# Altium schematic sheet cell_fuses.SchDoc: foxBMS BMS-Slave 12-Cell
size A3; DocumentNumber: 3; SheetNumber: 3; SheetTotal: 15; AUTHOR: Fraunhofer IISB foxBMS Team; SheetDescription: Cell Voltage Sense Fuses
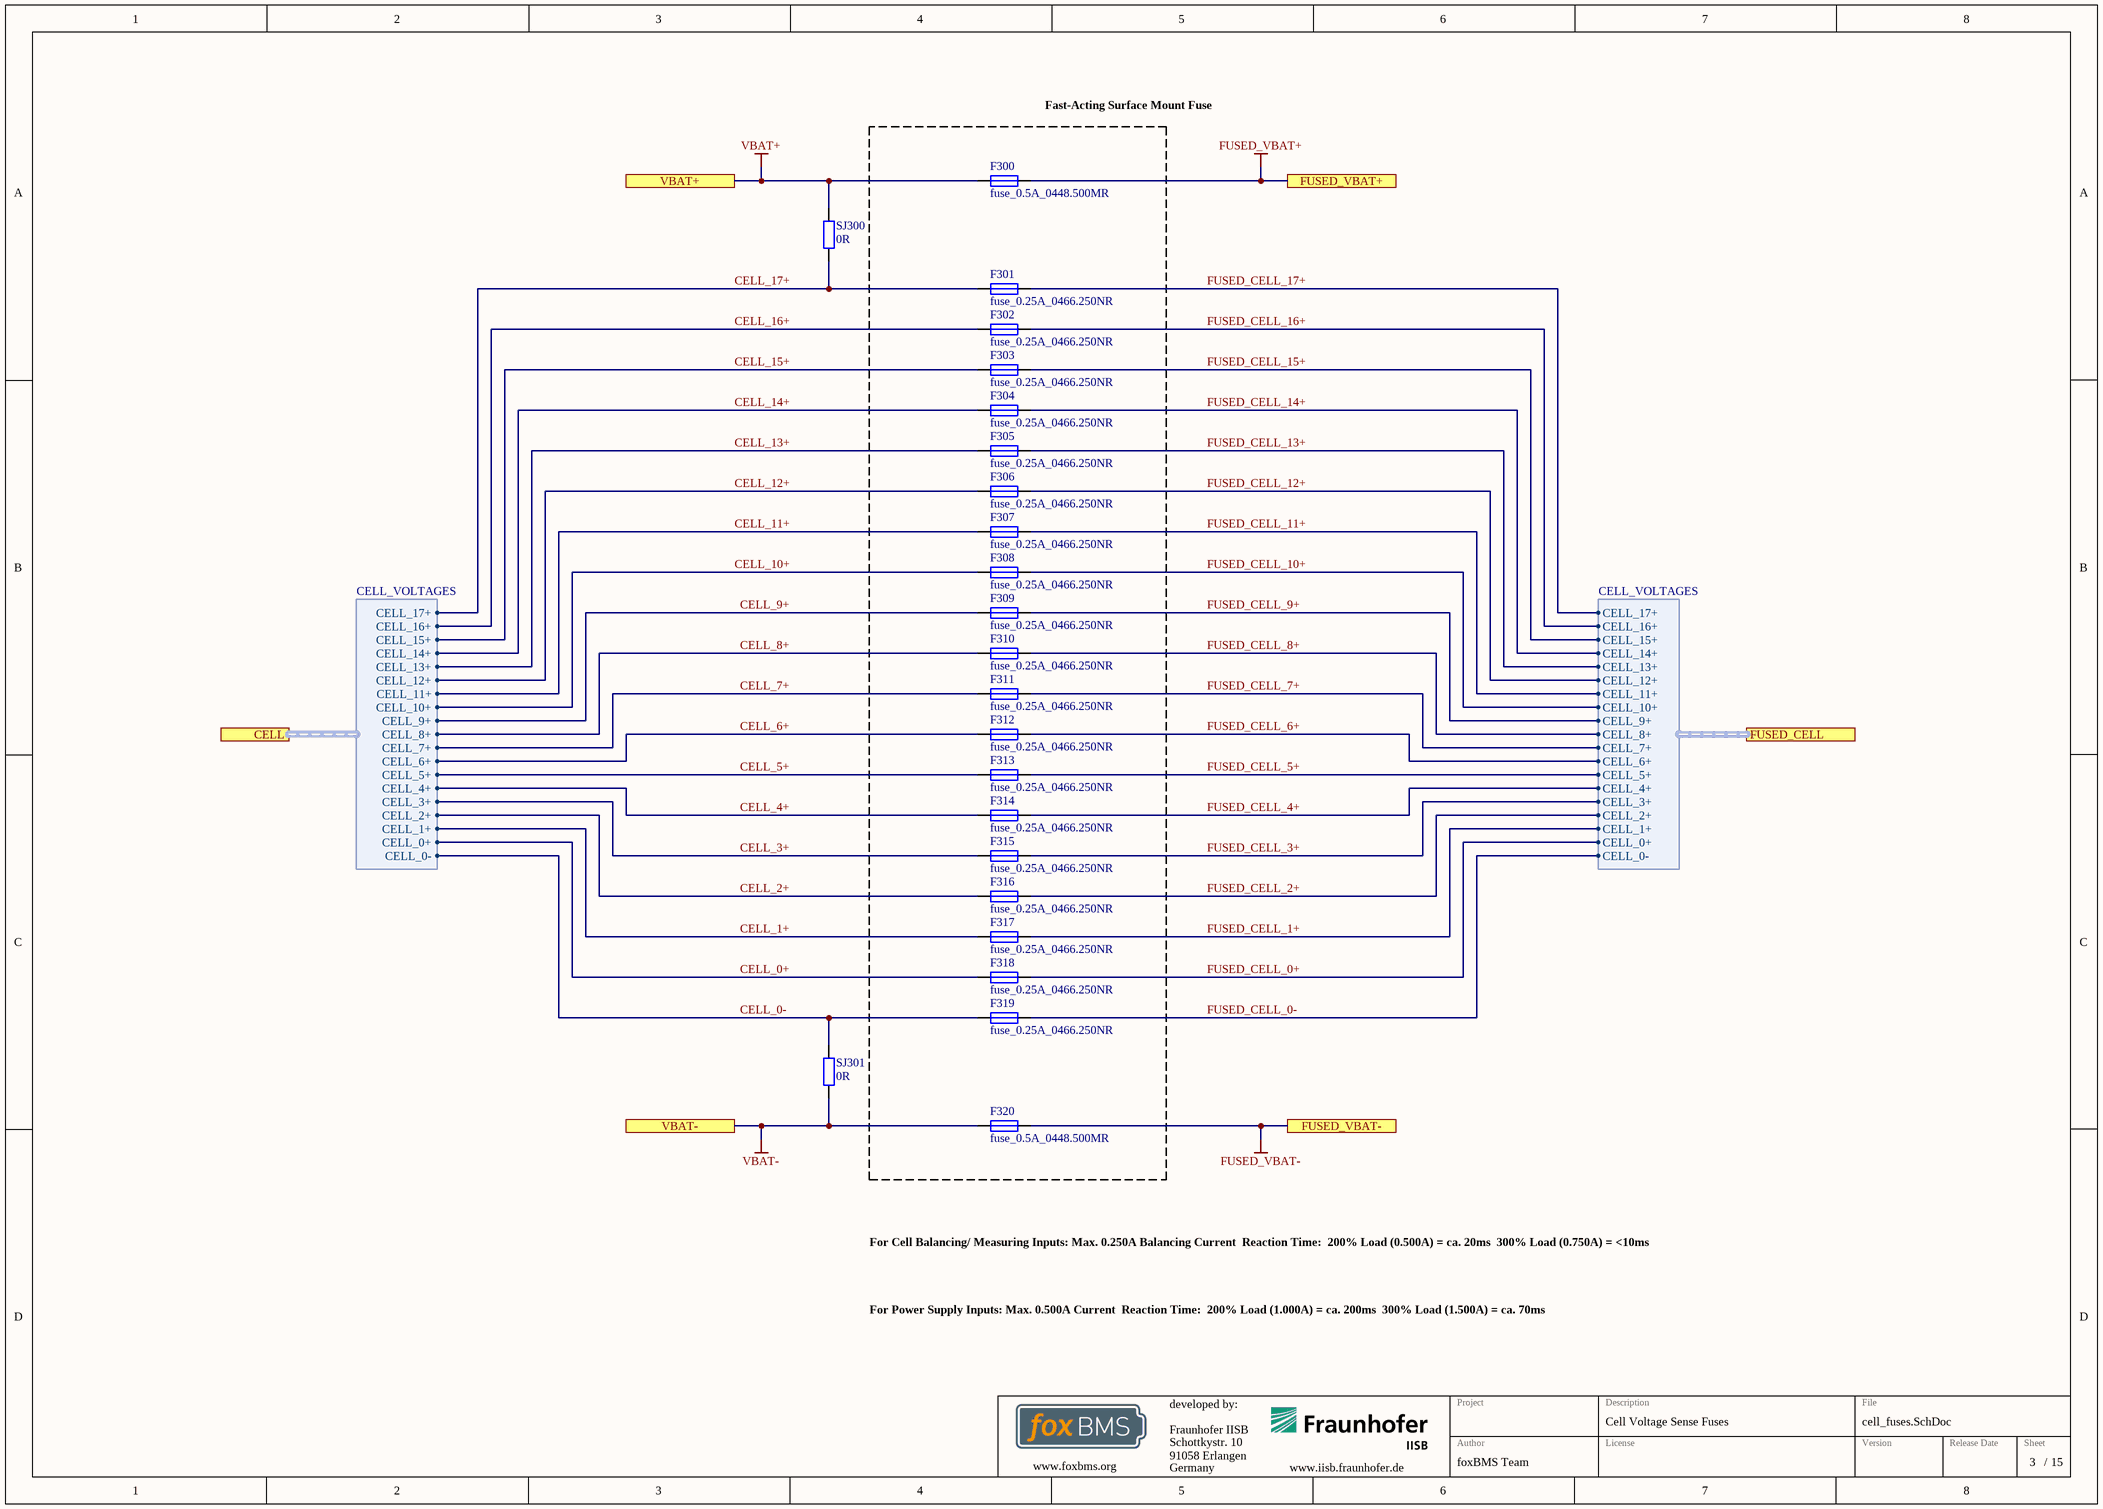
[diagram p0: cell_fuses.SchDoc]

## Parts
F300  fuse_0.5A_0448.500MR  [LITTLEFUSE_448]
F301  fuse_0.25A_0466.250NR  [LITTLEFUSE_466]
F302  fuse_0.25A_0466.250NR  [LITTLEFUSE_466]
F303  fuse_0.25A_0466.250NR  [LITTLEFUSE_466]
F304  fuse_0.25A_0466.250NR  [LITTLEFUSE_466]
F305  fuse_0.25A_0466.250NR  [LITTLEFUSE_466]
F306  fuse_0.25A_0466.250NR  [LITTLEFUSE_466]
F307  fuse_0.25A_0466.250NR  [LITTLEFUSE_466]
F308  fuse_0.25A_0466.250NR  [LITTLEFUSE_466]
F309  fuse_0.25A_0466.250NR  [LITTLEFUSE_466]
F310  fuse_0.25A_0466.250NR  [LITTLEFUSE_466]
F311  fuse_0.25A_0466.250NR  [LITTLEFUSE_466]
F312  fuse_0.25A_0466.250NR  [LITTLEFUSE_466]
F313  fuse_0.25A_0466.250NR  [LITTLEFUSE_466]
F314  fuse_0.25A_0466.250NR  [LITTLEFUSE_466]
F315  fuse_0.25A_0466.250NR  [LITTLEFUSE_466]
F316  fuse_0.25A_0466.250NR  [LITTLEFUSE_466]
F317  fuse_0.25A_0466.250NR  [LITTLEFUSE_466]
F318  fuse_0.25A_0466.250NR  [LITTLEFUSE_466]
F319  fuse_0.25A_0466.250NR  [LITTLEFUSE_466]
F320  fuse_0.5A_0448.500MR  [LITTLEFUSE_448]
SJ300  0R  [RESC1608X05N]
SJ301  0R  [RESC1608X05N]

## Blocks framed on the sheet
Fast-Acting Surface Mount Fuse: F300-F320

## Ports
CELL (harness CELL_VOLTAGES), FUSED_CELL (harness CELL_VOLTAGES), FUSED_VBAT+, FUSED_VBAT-, VBAT+, VBAT-

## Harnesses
CELL_VOLTAGES: CELL_0-, CELL_0+, CELL_1+, CELL_10+, CELL_11+, CELL_12+, CELL_13+, CELL_14+, CELL_15+, CELL_16+, CELL_17+, CELL_2+, CELL_3+, CELL_4+, CELL_5+, CELL_6+, CELL_7+, CELL_8+, CELL_9+

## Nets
FUSED_VBAT+: F300.2 ; port FUSED_VBAT+
FUSED_VBAT-: F320.2 ; port FUSED_VBAT-
VBAT+: F300.1 SJ300.1 ; port VBAT+
VBAT-: F320.1 SJ301.2 ; port VBAT-
CELL_0+: F318.1 ; port CELL.CELL_0+
CELL_0-: F319.1 SJ301.1 ; port CELL.CELL_0-
CELL_1+: F317.1 ; port CELL.CELL_1+
CELL_2+: F316.1 ; port CELL.CELL_2+
CELL_3+: F315.1 ; port CELL.CELL_3+
CELL_4+: F314.1 ; port CELL.CELL_4+
CELL_5+: F313.1 ; port CELL.CELL_5+
CELL_6+: F312.1 ; port CELL.CELL_6+
CELL_7+: F311.1 ; port CELL.CELL_7+
CELL_8+: F310.1 ; port CELL.CELL_8+
CELL_9+: F309.1 ; port CELL.CELL_9+
CELL_10+: F308.1 ; port CELL.CELL_10+
CELL_11+: F307.1 ; port CELL.CELL_11+
CELL_12+: F306.1 ; port CELL.CELL_12+
CELL_13+: F305.1 ; port CELL.CELL_13+
CELL_14+: F304.1 ; port CELL.CELL_14+
CELL_15+: F303.1 ; port CELL.CELL_15+
CELL_16+: F302.1 ; port CELL.CELL_16+
CELL_17+: F301.1 SJ300.2 ; port CELL.CELL_17+
FUSED_CELL_0+: F318.2 ; port FUSED_CELL.CELL_0+
FUSED_CELL_0-: F319.2 ; port FUSED_CELL.CELL_0-
FUSED_CELL_1+: F317.2 ; port FUSED_CELL.CELL_1+
FUSED_CELL_2+: F316.2 ; port FUSED_CELL.CELL_2+
FUSED_CELL_3+: F315.2 ; port FUSED_CELL.CELL_3+
FUSED_CELL_4+: F314.2 ; port FUSED_CELL.CELL_4+
FUSED_CELL_5+: F313.2 ; port FUSED_CELL.CELL_5+
FUSED_CELL_6+: F312.2 ; port FUSED_CELL.CELL_6+
FUSED_CELL_7+: F311.2 ; port FUSED_CELL.CELL_7+
FUSED_CELL_8+: F310.2 ; port FUSED_CELL.CELL_8+
FUSED_CELL_9+: F309.2 ; port FUSED_CELL.CELL_9+
FUSED_CELL_10+: F308.2 ; port FUSED_CELL.CELL_10+
FUSED_CELL_11+: F307.2 ; port FUSED_CELL.CELL_11+
FUSED_CELL_12+: F306.2 ; port FUSED_CELL.CELL_12+
FUSED_CELL_13+: F305.2 ; port FUSED_CELL.CELL_13+
FUSED_CELL_14+: F304.2 ; port FUSED_CELL.CELL_14+
FUSED_CELL_15+: F303.2 ; port FUSED_CELL.CELL_15+
FUSED_CELL_16+: F302.2 ; port FUSED_CELL.CELL_16+
FUSED_CELL_17+: F301.2 ; port FUSED_CELL.CELL_17+

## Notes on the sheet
- For Cell Balancing/ Measuring Inputs: Max. 0.250A Balancing Current
  Reaction Time:
  200% Load (0.500A) = ca. 20ms
  300% Load (0.750A) = <10ms
- For Power Supply Inputs: Max. 0.500A Current
  Reaction Time:
  200% Load (1.000A) = ca. 200ms
  300% Load (1.500A) = ca. 70ms

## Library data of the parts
F300 F320 = fuse_0.5A_0448.500MR: Fuse, Surface Mount, NANO2 Series, 500 mA, 125 VAC, 32 VDC, Very Fast Acting, SMD; Manufacturer: Littlefuse; Automotive Qualified: False
F301-F319 = fuse_0.25A_0466.250NR: Fuse, Surface Mount, 466 Series, 250 mA, 125 VAC, 125 VDC, Very Fast Acting, 1206; Manufacturer: Littlefuse; Automotive Qualified: False
SJ300 SJ301 = gen_R_0R_0603: SMD Resistor 0R 0603; Power: 0.1W; Case EIA: 0603; Case Metric: 1608; Maximum Working Voltage: 75V; PnP Package: R_0603; Automotive Qualified: True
